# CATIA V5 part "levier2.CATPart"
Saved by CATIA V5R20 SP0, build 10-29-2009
Part number: levier2
Bounding box of the stored display mesh (mm): x -20 to 20, y -109.993 to 200.381, z 881.949 to 1269.993
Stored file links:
  D:\Dropbox\Pack 1 sylvain\mmoreau\mmoreau\mmoreau\fin\levier2.CATPart
  U:\think motion\fin\think motion2.CATProduct
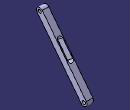
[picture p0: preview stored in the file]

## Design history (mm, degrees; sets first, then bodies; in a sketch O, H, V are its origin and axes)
External parameters (linked from other documents)
  `External.largeur levier` = 40 mm
Set1
  Plane1: linked copy from another document
  Line1: linked copy from another document
  Point1 to Point3: linked copy from another document
  Line2: linked copy from another document
Body1 (main body)
  Sketch1 on Plane1, origin (0, 0, 0), H (0, 1, 0), V (0, 0, 1)
    line L1 (-74.2058, 1262.2697) -> (196.1825, 914.2116)
    reference projected line E1 (-51.3303, 1200.2224) -> (512.5218, 474.4025) from Line1
    arc A1 centre (-90, 1250) radius 20 from (-74.2058, 1262.2697) to (-105.7942, 1237.7303) ccw
    point P1 (-90, 1250)
    reference projected point E2 (-90, 1250) from Point1
    arc A2 centre (180.3884, 901.9419) radius 20 from (164.5942, 889.6723) to (196.1825, 914.2116) ccw
    point P2 (180.3884, 901.9419)
    reference projected point E3 (180.3884, 901.9419) from Point2
    point P3 (-74.2058, 1262.2697)
    point P4 (196.1825, 914.2116)
    reference projected line E4 (-90, 1250) -> (180.3884, 901.9419) from edge of Line1
    point P7 (164.5942, 889.6723)
    point P8 (-105.7942, 1237.7303)
    line L2 (-105.7942, 1237.7303) -> (164.5942, 889.6723)
    circle A3 centre (-90, 1250) radius 10
    point P9 (-90, 1250)
    reference projected point E5 (-90, 1250) from Point1
    circle A4 centre (180.3884, 901.9419) radius 10
    point P10 (180.3884, 901.9419)
    reference projected point E6 (180.3884, 901.9419) from Point2
    radius A3 = 10
    radius A4 = 10
    distance E4 L1 = 20
    parallelism: L1 E1
    tangency: A1 L1, A2 L1
    coincidence: P1 E2, P2 E3, E5 P9, P10 E4, P10 E6
    symmetry: P4 P7 E4, P3 P8 E4, L1 L2 E4
  Pad1: profile Sketch1, direction (1, 0, 0), length 20 {= `External.largeur levier` /2}, mirrored extent
  Sketch2 on face of Pad1 from Sketch1.L1, origin (0, 565.2573, 439.1193), H (-1, 0, 0), V (0, -0.6135, 0.7897)
    construction line L1 (0, 894.165) -> (0, 794.165)
    point P1 (0, 894.165)
    point P2 (0, 794.165)
    line L2 (15, 894.165) -> (15, 794.165)
    line L3 (-15, 794.165) -> (-15, 894.165)
    arc A1 centre (0, 794.165) radius 15 from (15, 794.165) to (-15, 794.165) cw
    arc A2 centre (0, 894.165) radius 15 from (-15, 894.165) to (15, 894.165) cw
    reference projected line E1 (0, 1042.3481) -> (0, 601.6053) from Line1
    reference projected point E2 (0, 894.165) from Point3
    reference projected point E3 (0, 894.165) from Point3
    distance L3 L2 = 30
    distance P1 E2 = 0
    distance P2 E3 = 100
    vertical: L1 V
    tangency: A1 L2, A2 L2, A1 L3, A2 L3
    coincidence: L1 E1
  Pocket1: profile Sketch2, direction (0, -0.7897, -0.6135), through (limit type 6)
